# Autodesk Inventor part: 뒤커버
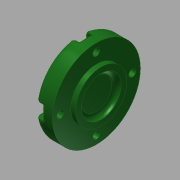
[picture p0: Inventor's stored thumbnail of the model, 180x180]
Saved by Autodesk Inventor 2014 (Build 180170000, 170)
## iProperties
Created: 2015-11
Part Number: 뒤커버
Material: 알루미늄 6061
Document SubType Name: Modeling
Designer: mduedu
Density: 1 g/cm^3
Appearance: Smooth - Dark Forest Green
Author: mduedu
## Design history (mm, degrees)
sketch "스케치1"
  geometry: L1 (-7, 0)-(7, 0); L2 (-7, 0)-(-7, 27.5); L3 (-7, 27.5)-(4, 27.5); L4 (4, 27.5)-(4, 16); L5 (4, 16)-(7, 16); L6 (7, 16)-(7, 0); 2 further points
  constraints: 12 end point, 3 perpendicular, 2 parallel, 1 coincident, 1 horizontal, 1 midpoint
  dimensions: "d0" = 14 distance of L1.start L1.end; "d1" = 55 diameter of L3 L1; "d2" = 3 distance of L4.end L5.end; "d3" = 32 diameter of L5 L1
revolve "회전1" sketch "스케치1" stored, may be unused: angle "d4" = 90 deg
hole "구멍1" diameter "d7" = 25; stored, may be unused: countersink angle "d11" = 90 deg, drill point angle "d13" = 0 deg; dims "d5" = 10, "d6" = 10, "d8" = 6, "d9" = 4, "d10" = 2, "d12" = 3
fillet "모깎기2" dims "d36" = 3
fillet "모깎기3" dims "d37" = 3
sketch "스케치2" dims "d39" = 45
  geometry: C1 r 12.846 at (0, 0) reference; C2 r 24.5 at (0, 0) reference; 6 further points
  constraints: 2 vertical alignment, 1 coincident, 7 other
  dimensions: "d42" = 360 deg dimension on point (0, 0) point (0, 22.5) (derived)
sketch "스케치3"
  geometry: 8 further points
  constraints: 4 coincident
hole "구멍4" sketch "스케치3" at (-22.5, 0), (0, -22.5), (22.5, 0), (0, 22.5) diameter "d44" = 4.5; stored, may be unused: countersink angle "d48" = 90 deg, drill point angle "d50" = 0 deg; dims "d45" = 6, "d46" = 8, "d47" = 4.6, "d49" = 8
sketch "스케치4"
  geometry: L1 (-4, 0)-(-4, -4.708); L2 (4, 0)-(4, -4.708); A1 r 4 centre (0, 0) between (-4, 0) and (4, 0) reference; A2 r 27.5 centre (0, 22.5) between (-4, -4.708) and (4, -4.708) reference; 3 further points
  constraints: 4 end point, 4 point on circle, 2 tangent, 1 parallel, 1 vertical
extrude "돌출1" cut sketch "스케치4" stored distance "d51" = 0; taper "d52" = 0 deg
fillet "모깎기5" dims "d56" = 0.3
fillet "모깎기6" dims "d57" = 1
node "솔리드1"
pattern_circular "원형 패턴1" dims angle "d54" = 360 deg
